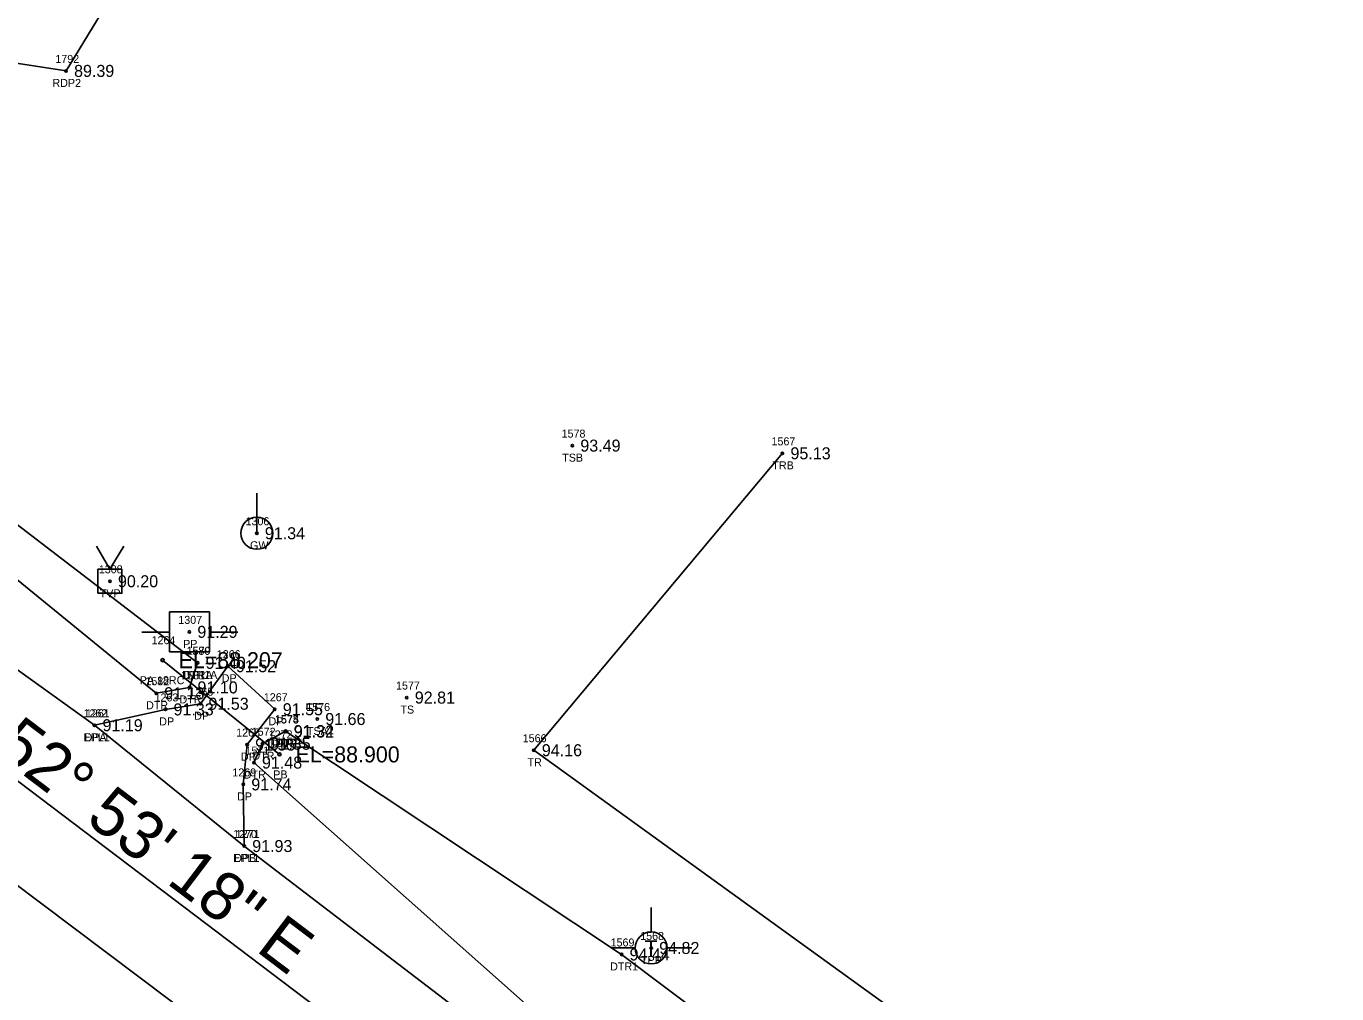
# Model space of a CAD drawing. Extents: x 2529517 to 2532038, y 935000 to 936944.
# Drawn here: x 2531867.5 to 2532031.2, y 936230.7 to 936351.6 of the extents above; entities that cross this region are included whole.
import ezdxf

# ---------------------------------------------------------------- set-up
doc = ezdxf.new("R2010")
doc.units = 0
for name, color, linetype in [('Default', 7, 'Continuous'), ('RD_DTM_BkLn_txCode', 7, 'Continuous'), ('RD_EX_DR_ErosCtrl', 7, 'Continuous'), ('RD_EX_DR_ErosCtrl_txCode', 7, 'Continuous'), ('RD_EX_DR_Pipe', 7, 'Continuous'), ('RD_EX_DR_Pipe_txCode', 7, 'Continuous'), ('RD_EX_Driveway', 7, 'Continuous'), ('RD_EX_Driveway_txCode', 7, 'Continuous'), ('RD_EX_H2O', 7, 'Continuous'), ('RD_EX_H2O_txCode', 7, 'Continuous'), ('RD_EX_Road', 7, 'Continuous'), ('RD_EX_Road_txCode', 7, 'Continuous'), ('RD_EX_TX_DR_ErosCtrl_ELEV', 7, 'Continuous'), ('RD_EX_TX_Driveway_ELEV', 7, 'Continuous'), ('RD_EX_TX_H2O_ELEV', 7, 'Continuous'), ('RD_EX_TX_Misc_ELEV', 7, 'Continuous'), ('RD_EX_TX_Road_ELEV', 7, 'Continuous'), ('RD_EX_TX_UT_ELEV', 7, 'Continuous'), ('RD_EX_TX_VEG_ELEV', 7, 'Continuous'), ('RD_EX_UT', 7, 'Continuous'), ('RD_EX_UT_txCode', 7, 'Continuous'), ('RD_EX_VEG', 7, 'Continuous'), ('RD_EX_VEG_txCode', 7, 'Continuous'), ('RD_HC_Cl', 7, 'Continuous'), ('RD_HC_Data', 7, 'Continuous'), ('RD_HC_Survey_ELEV', 7, 'Continuous'), ('RD_SMD_Locator', 7, 'Continuous'), ('RD_TX_Pipe_ElevEX', 7, 'Continuous')]:
    doc.layers.add(name, color=color, linetype=linetype)

msp = doc.modelspace()

# ---------------------------------------------------------------- linework, layer by layer
at = {"layer": 'Default'}
msp.add_line((2531759.99, 936337.77), (2531999.23, 936156.76), dxfattribs=at)
at = {"layer": 'RD_EX_DR_ErosCtrl'}
msp.add_lwpolyline([(2531826.03, 936317.37), (2531842.02, 936350.64), (2531872.46, 936345.98), (2531906.05, 936401.13), (2531944.32, 936458.1), (2531968.34, 936447.83), (2531976.81, 936458.99), (2531957.81, 936476.14), (2531966.51, 936493.14)], dxfattribs=at)
at = {"layer": 'RD_EX_DR_Pipe'}
msp.add_line((2531884.51, 936272.35), (2531899.12, 936260.58), dxfattribs=at)
at = {"layer": 'RD_EX_Driveway'}
msp.add_lwpolyline([(2531876.01, 936264.22), (2531884.88, 936266.2), (2531889.25, 936266.91), (2531892.68, 936271.6), (2531898.53, 936266.22), (2531895.08, 936261.81), (2531894.6, 936256.83), (2531894.71, 936249.13)], dxfattribs=at)
at = {"layer": 'RD_EX_H2O'}
for points in [[(2531888.89, 936272.02), (2531858.16, 936295.56), (2531826.03, 936317.37), (2531815.27, 936323.11)], [(2531888.89, 936272.02), (2531887.88, 936268.95), (2531883.72, 936268.22), (2531855.58, 936291.19), (2531822.13, 936313.28), (2531815.27, 936323.11)], [(2532013.59, 936164.05), (2531933.99, 936225.75), (2531895.93, 936259.56), (2531897, 936261.91), (2531899.89, 936263.49), (2531899.92, 936263.44)], [(2532021.52, 936175.64), (2531941.85, 936235.58), (2531899.92, 936263.44)]]:
    msp.add_lwpolyline(points, dxfattribs=at)
at = {"layer": 'RD_EX_Road'}
for points in [[(2531788.67, 936375.53), (2531784.05, 936361.55), (2531786.68, 936344.28), (2531790.66, 936334.1), (2531795.41, 936327.11), (2531801.08, 936320.84), (2531849.6, 936283.17), (2531876.01, 936264.22), (2531894.71, 936249.13), (2531930.69, 936221.59), (2532010.91, 936160.51)], [(2531730.37, 936304.55), (2531747.09, 936311.1), (2531758.83, 936311.42), (2531770.03, 936309.95), (2531779.92, 936307.38), (2531789.77, 936300.82), (2531836.93, 936266.34), (2531918.06, 936205.29), (2531926.11, 936199.32), (2531961.6, 936172.59), (2531979.77, 936158.9), (2531999.31, 936144.02)]]:
    msp.add_lwpolyline(points, dxfattribs=at)
at = {"layer": 'RD_EX_UT'}
for p, q in [((2531896.29, 936288.21), (2531896.29, 936293.21)), ((2531877.94, 936283.71), (2531876.27, 936286.6)), ((2531877.94, 936283.71), (2531879.68, 936286.6)), ((2531890.36, 936278.4), (2531885.36, 936278.4)), ((2531885.36, 936278.4), (2531885.36, 936273.4)), ((2531890.36, 936273.4), (2531890.36, 936278.4)), ((2531881.92, 936275.84), (2531885.39, 936275.84)), ((2531890.28, 936275.84), (2531893.92, 936275.84)), ((2531885.36, 936273.4), (2531890.36, 936273.4)), ((2531945.55, 936241.46), (2531945.55, 936238.39)), ((2531940.62, 936236.41), (2531943.55, 936236.41)), ((2531947.55, 936236.41), (2531950.62, 936236.41))]:
    msp.add_line(p, q, dxfattribs=at)
msp.add_lwpolyline([(2531876.44, 936280.71), (2531876.44, 936283.71), (2531879.44, 936283.71), (2531879.44, 936280.71)], close=True, dxfattribs=at)
for centre in [(2531896.29, 936288.21), (2531945.55, 936236.39)]:
    msp.add_circle(centre, 2, dxfattribs=at)
at = {"layer": 'RD_EX_VEG'}
msp.add_lwpolyline([(2532031.19, 936188.58), (2531930.89, 936261.1), (2531961.95, 936298.2)], dxfattribs=at)
at = {"layer": 'RD_HC_Cl'}
msp.add_line((2531759.99, 936337.77), (2531999.23, 936156.76), dxfattribs=at)
at = {"layer": 'RD_SMD_Locator'}
for centre, radius in [((2531872.46, 936345.98), 0.15), ((2531935.7, 936299.16), 0.15), ((2531961.95, 936298.2), 0.15), ((2531896.29, 936288.21), 0.15), ((2531877.94, 936282.21), 0.15), ((2531887.86, 936275.89), 0.15), ((2531884.51, 936272.35), 0.2), ((2531888.89, 936272.02), 0.15), ((2531888.89, 936272.02), 0.15), ((2531892.68, 936271.6), 0.15), ((2531883.72, 936268.22), 0.15), ((2531887.88, 936268.95), 0.15), ((2531889.25, 936266.91), 0.15), ((2531915.02, 936267.68), 0.15), ((2531884.88, 936266.2), 0.15), ((2531898.53, 936266.22), 0.15), ((2531903.84, 936265), 0.15), ((2531876.01, 936264.22), 0.15), ((2531876.01, 936264.22), 0.15), ((2531899.89, 936263.49), 0.15), ((2531899.92, 936263.44), 0.15), ((2531899.92, 936263.44), 0.15), ((2531895.08, 936261.81), 0.15), ((2531897, 936261.91), 0.15), ((2531899.12, 936260.58), 0.2), ((2531930.89, 936261.1), 0.15), ((2531895.93, 936259.56), 0.15), ((2531894.6, 936256.83), 0.15), ((2531894.71, 936249.13), 0.15), ((2531894.71, 936249.13), 0.15), ((2531941.85, 936235.58), 0.15), ((2531945.55, 936236.39), 0.15)]:
    msp.add_circle(centre, radius, dxfattribs=at)

# ---------------------------------------------------------------- texts
at = {"layer": 'RD_DTM_BkLn_txCode'}
for s, p in [('1578', (2531934.36, 936300.16)), ('TSB', (2531934.44, 936297.16)), ('1577', (2531913.68, 936268.68)), ('1576', (2531902.46, 936266)), ('TS', (2531914.23, 936265.68)), ('TSA', (2531902.55, 936263))]:
    msp.add_text(s, height=1, dxfattribs=at).set_placement(p)
at = {"layer": 'RD_EX_DR_ErosCtrl_txCode'}
for s, p in [('1792', (2531871.12, 936346.98)), ('RDP2', (2531870.76, 936343.98))]:
    msp.add_text(s, height=1, dxfattribs=at).set_placement(p)
at = {"layer": 'RD_EX_DR_Pipe_txCode'}
for s, p in [('1264', (2531883.14, 936274.35)), ('PA 18RC', (2531881.66, 936269.35)), ('1272', (2531897.77, 936262.58)), ('PB', (2531898.34, 936257.58))]:
    msp.add_text(s, height=1, dxfattribs=at).set_placement(p)
at = {"layer": 'RD_EX_Driveway_txCode'}
for s, p in [('1266', (2531891.28, 936272.6)), ('DP', (2531891.9, 936269.6)), ('1265', (2531887.88, 936267.91)), ('1263', (2531883.51, 936267.2)), ('1267', (2531897.16, 936267.22)), ('1262', (2531874.64, 936265.22)), ('DP', (2531884.1, 936264.2)), ('DP', (2531888.47, 936264.91)), ('DP', (2531897.75, 936264.22)), ('1268', (2531893.71, 936262.81)), ('DPA', (2531874.75, 936262.22)), ('DP', (2531894.3, 936259.81)), ('1269', (2531893.23, 936257.83)), ('DP', (2531893.82, 936254.83)), ('1270', (2531893.33, 936250.13)), ('DPB', (2531893.46, 936247.13))]:
    msp.add_text(s, height=1, dxfattribs=at).set_placement(p)
at = {"layer": 'RD_EX_H2O_txCode'}
for s, p in [('1580', (2531887.5, 936273.02)), ('1579', (2531887.54, 936273.02)), ('1582', (2531882.37, 936269.22)), ('1581', (2531886.82, 936269.95)), ('DTR1A', (2531886.97, 936270.02)), ('DTRA', (2531887.13, 936270.02)), ('DTR', (2531882.45, 936266.22)), ('DTR', (2531886.62, 936266.95)), ('1573', (2531898.54, 936264.49)), ('1574', (2531898.57, 936264.44)), ('1575', (2531898.57, 936264.44)), ('1572', (2531895.65, 936262.91)), ('DTR1B', (2531898.01, 936261.44)), ('DTRB', (2531898.18, 936261.44)), ('DTR', (2531898.62, 936261.49)), ('1571', (2531894.87, 936260.56)), ('DTR', (2531895.73, 936259.91)), ('DTR', (2531894.66, 936257.56)), ('1569', (2531940.48, 936236.58)), ('DTR1', (2531940.42, 936233.58))]:
    msp.add_text(s, height=1, dxfattribs=at).set_placement(p)
at = {"layer": 'RD_EX_Road_txCode'}
for s, p in [('1261', (2531874.93, 936265.22)), ('EPL1', (2531874.64, 936262.22)), ('1271', (2531893.65, 936250.13)), ('EPL1', (2531893.34, 936247.13))]:
    msp.add_text(s, height=1, dxfattribs=at).set_placement(p)
at = {"layer": 'RD_EX_TX_DR_ErosCtrl_ELEV'}
msp.add_text('89.39', height=1.5, dxfattribs=at).set_placement((2531873.46, 936345.23))
at = {"layer": 'RD_EX_TX_Driveway_ELEV'}
for s, p in [('91.52', (2531893.68, 936270.85)), ('91.33', (2531885.88, 936265.45)), ('91.53', (2531890.25, 936266.16)), ('91.55', (2531899.53, 936265.47)), ('91.19', (2531877.01, 936263.47)), ('91.55', (2531896.08, 936261.06)), ('91.74', (2531895.6, 936256.08)), ('91.93', (2531895.71, 936248.38))]:
    msp.add_text(s, height=1.5, dxfattribs=at).set_placement(p)
at = {"layer": 'RD_EX_TX_H2O_ELEV'}
for s, p in [('91.40', (2531889.89, 936271.27)), ('91.40', (2531889.89, 936271.27)), ('91.13', (2531884.72, 936267.47)), ('91.10', (2531888.88, 936268.2)), ('91.34', (2531900.89, 936262.74)), ('91.32', (2531900.92, 936262.69)), ('91.32', (2531900.92, 936262.69)), ('91.35', (2531898, 936261.16)), ('91.48', (2531896.93, 936258.81)), ('94.44', (2531942.85, 936234.83))]:
    msp.add_text(s, height=1.5, dxfattribs=at).set_placement(p)
at = {"layer": 'RD_EX_TX_Misc_ELEV'}
for s, p in [('93.49', (2531936.7, 936298.41)), ('92.81', (2531916.02, 936266.93)), ('91.66', (2531904.84, 936264.25))]:
    msp.add_text(s, height=1.5, dxfattribs=at).set_placement(p)
at = {"layer": 'RD_EX_TX_Road_ELEV'}
for s, p in [('91.19', (2531877.01, 936263.47)), ('91.93', (2531895.71, 936248.38))]:
    msp.add_text(s, height=1.5, dxfattribs=at).set_placement(p)
at = {"layer": 'RD_EX_TX_UT_ELEV'}
for s, p in [('91.34', (2531897.29, 936287.46)), ('90.20', (2531878.94, 936281.46)), ('94.82', (2531946.55, 936235.64))]:
    msp.add_text(s, height=1.5, dxfattribs=at).set_placement(p)
at = {"layer": 'RD_EX_TX_VEG_ELEV'}
for s, p in [('95.13', (2531962.95, 936297.45)), ('94.16', (2531931.89, 936260.35))]:
    msp.add_text(s, height=1.5, dxfattribs=at).set_placement(p)
at = {"layer": 'RD_EX_UT'}
msp.add_text('T', height=2, dxfattribs=at).set_placement((2531944.7, 936235.34))
at = {"layer": 'RD_EX_UT_txCode'}
for s, p in [('1306', (2531894.88, 936289.21)), ('GW', (2531895.44, 936286.21)), ('1308', (2531876.55, 936283.21)), ('TVP', (2531876.66, 936280.21)), ('1307', (2531886.48, 936276.89)), ('PP', (2531887.08, 936273.89)), ('1568', (2531944.18, 936237.39)), ('TPP', (2531944.28, 936234.39))]:
    msp.add_text(s, height=1, dxfattribs=at).set_placement(p)
at = {"layer": 'RD_EX_VEG_txCode'}
for s, p in [('1567', (2531960.58, 936299.2)), ('TRB', (2531960.69, 936296.2)), ('1566', (2531929.5, 936262.1)), ('TR', (2531930.1, 936259.1))]:
    msp.add_text(s, height=1, dxfattribs=at).set_placement(p)
at = {"layer": 'RD_HC_Data'}
msp.add_text('S 52%%d 53\' 18" E', height=6, rotation=322.8882, dxfattribs=at).set_placement((2531857.25, 936265.44))
at = {"layer": 'RD_HC_Survey_ELEV'}
msp.add_text('91.29', height=1.5, dxfattribs=at).set_placement((2531888.86, 936275.14))
at = {"layer": 'RD_TX_Pipe_ElevEX'}
for s, p in [('EL=88.207', (2531886.51, 936271.35)), ('EL=88.900', (2531901.12, 936259.58))]:
    msp.add_text(s, height=2, dxfattribs=at).set_placement(p)

doc.saveas('drawing.dxf')
